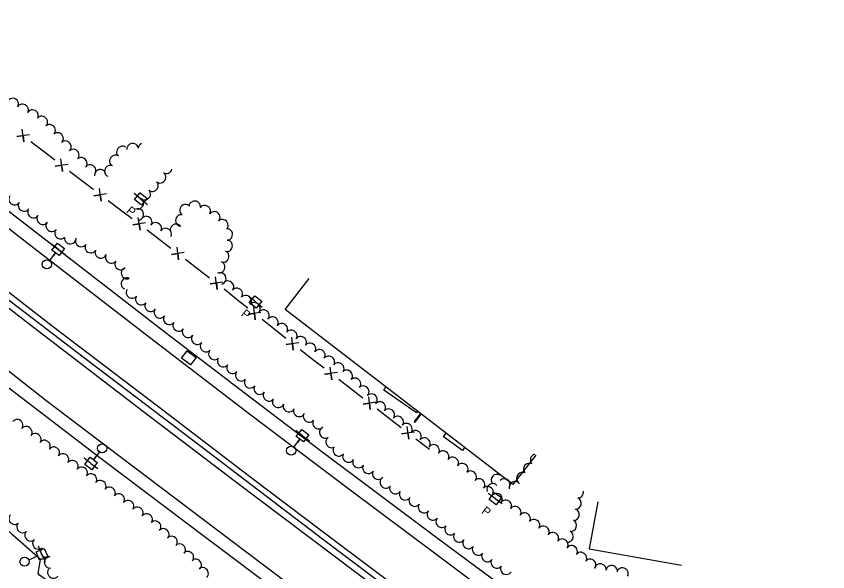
# Model space of a CAD drawing. Extents: x 1746010 to 1754829, y 655801 to 663091.
# Drawn here: x 1749717 to 1750426, y 660347 to 660832 of the extents above; entities that cross this region are included whole.
import ezdxf

# ---------------------------------------------------------------- set-up
doc = ezdxf.new("R2010")
doc.units = 0
for name, color, linetype in [('SURVEY - AERIAL SURVEY - Photo Control - Points - Locators', 7, 'Continuous'), ('SURVEY - AERIAL SURVEY - Photo Control - Points - Numbers', 7, 'Continuous'), ('SURVEY - CENTERLINE - Existing Roads - Development', 7, 'Continuous'), ('SURVEY - CENTERLINE - Existing Roads Curve Text', 7, 'Continuous'), ('SURVEY - CENTERLINE - Existing Roads Text', 7, 'Continuous'), ('SURVEY - CENTERLINE - Preliminary - Development', 7, 'Continuous')]:
    doc.layers.add(name, color=color, linetype=linetype)

msp = doc.modelspace()

# ---------------------------------------------------------------- linework, layer by layer
at = {"layer": 'SURVEY - AERIAL SURVEY - Photo Control - Points - Locators'}
for points in [[(1749387.11, 660899.35), (1749486.53, 660821.3), (1749560.37, 660763.13), (1749636.02, 660704.45), (1749732.4, 660629.58), (1749833.07, 660551.99), (1749920.33, 660484.88), (1750008.5, 660418.55), (1750084.45, 660361.56), (1750166.82, 660299.99), (1750252.84, 660236.3), (1750339.47, 660172.61), (1750424.46, 660110.17), (1750505.09, 660051.79), (1750510.03, 660048.27)], [(1750422.34, 660058.69), (1750341.81, 660116.67), (1750243.85, 660188.2), (1750158.07, 660251.54), (1750079.76, 660310), (1749998.95, 660370.82), (1749924.19, 660427.29), (1749840.05, 660491.49), (1749747.97, 660561.59), (1749667.56, 660623.87), (1749593.96, 660681.21), (1749510.38, 660746.53), (1749431.04, 660809.06), (1749359.66, 660865.36)], [(1749353.21, 660856.72), (1749450.09, 660780.53), (1749529.69, 660717.36), (1749638.4, 660632.78), (1749725.25, 660565.49), (1749826.74, 660487.69), (1749908.21, 660425.76), (1750015.78, 660344.74), (1750134.74, 660255.49), (1750241.73, 660176.3), (1750327.29, 660113.27), (1750398.53, 660061.52)], [(1750309.34, 660072.12), (1750268.26, 660102.16), (1750202.16, 660151.04), (1750125.31, 660207.81), (1750054.71, 660260.76), (1749978.89, 660317.54), (1749904.25, 660374.13), (1749807.5, 660447.32), (1749742.59, 660496.65), (1749689.97, 660537.57), (1749628.45, 660585.34), (1749555.8, 660641.5), (1749484.89, 660697.07), (1749405.47, 660759.79), (1749328.25, 660820.51)], [(1750288.61, 660074.58), (1750206.58, 660134.59), (1750105.78, 660208.88), (1750014.16, 660277.34), (1749883.11, 660375.92), (1749790.93, 660445.43), (1749702.19, 660513.29), (1749634.54, 660565.49), (1749547.88, 660632.78), (1749453.06, 660707.08), (1749311.71, 660816.35)], [(1749949.53, 660142.04), (1749959.68, 660175.76), (1749908.29, 660214.04), (1749859.35, 660250.31), (1749801, 660295.27), (1749769.71, 660320.03), (1749752.54, 660333.06), (1749741.05, 660341.05), (1749737.1, 660343.79), (1749735.68, 660345.35), (1749737.91, 660357.63), (1749713.32, 660379), (1749684.22, 660407.06), (1749658.62, 660430.58), (1749636.39, 660450.84), (1749625.75, 660457.9), (1749494.88, 660556.97)]]:
    msp.add_lwpolyline(points, dxfattribs=at)
at = {"layer": 'SURVEY - AERIAL SURVEY - Photo Control - Points - Numbers'}
for points in [[(1750365.71, 660168.08), (1750350.37, 660178.69), (1750287.2, 660225.82), (1750205.37, 660286.01), (1750139.45, 660335.41), (1750086.68, 660374.49), (1749983.6, 660451.73), (1749923.2, 660497.58), (1749846.86, 660555.87), (1749777.3, 660609.82), (1749717.93, 660655.7), (1749636.62, 660718.64), (1749570.63, 660769.87), (1749510.15, 660817.71), (1749441.97, 660871.04), (1749371.15, 660927.67)], [(1749348.39, 660867.21), (1749450.14, 660787.41), (1749578.82, 660686.52), (1749682.3, 660605.65), (1749779.99, 660530.78), (1749879.01, 660455.62), (1749985.38, 660374.75), (1750084.31, 660300.06), (1750202.67, 660211.89), (1750354.74, 660100.39), (1750409.77, 660060.18)]]:
    msp.add_lwpolyline(points, dxfattribs=at)
at = {"layer": 'SURVEY - CENTERLINE - Existing Roads - Development'}
for points in [[(1749728.19, 660728.84), (1749717.05, 660727.32), (1749722.58, 660728.11), (1749723.31, 660722.5), (1749721.92, 660733.66)], [(1749741.31, 660713.59), (1749729.41, 660722.73)], [(1749750.35, 660706.64), (1749741.31, 660713.59)], [(1749761.89, 660702.94), (1749750.75, 660701.42), (1749756.28, 660702.21), (1749757.01, 660696.6), (1749755.62, 660707.76)], [(1749775.01, 660687.69), (1749763.11, 660696.83)], [(1749784.06, 660680.76), (1749781.98, 660682.33), (1749775.01, 660687.69)], [(1749795.64, 660677.2), (1749784.52, 660675.54), (1749790.04, 660676.4), (1749790.84, 660670.8), (1749789.32, 660681.94)], [(1749808.94, 660662.1), (1749796.95, 660671.1)], [(1749818.06, 660655.26), (1749808.94, 660662.1)], [(1749829.64, 660651.7), (1749818.52, 660650.04), (1749824.04, 660650.9), (1749824.84, 660645.3), (1749823.32, 660656.44)], [(1749842.82, 660636.43), (1749830.92, 660645.56)], [(1749851.86, 660629.49), (1749842.82, 660636.43)], [(1749863.4, 660625.8), (1749852.26, 660624.26), (1749857.79, 660625.06), (1749858.53, 660619.45), (1749857.14, 660630.61)], [(1749876.53, 660610.55), (1749864.64, 660619.69)], [(1749885.58, 660603.61), (1749876.53, 660610.55)], [(1749897.12, 660599.92), (1749885.98, 660598.39), (1749891.51, 660599.18), (1749892.25, 660593.57), (1749890.85, 660604.73)], [(1750170.45, 660448.8), (1750150.63, 660423.04), (1749951.68, 660576.14), (1749972.51, 660603.21)], [(1749910.01, 660584.37), (1749898.28, 660593.71)], [(1749918.93, 660577.26), (1749910.01, 660584.37)], [(1749930.4, 660573.37), (1749919.24, 660572.03), (1749924.78, 660572.73), (1749925.42, 660567.11), (1749924.22, 660578.29)], [(1749943.26, 660557.89), (1749931.53, 660567.23)], [(1749952.18, 660550.79), (1749943.26, 660557.89)], [(1749963.65, 660546.89), (1749952.49, 660545.56), (1749958.03, 660546.25), (1749958.67, 660540.63), (1749957.47, 660551.81)], [(1749976.69, 660531.64), (1749964.82, 660540.82)], [(1749985.71, 660524.67), (1749976.69, 660531.64)], [(1749997.24, 660520.94), (1749986.09, 660519.44), (1749991.62, 660520.22), (1749992.34, 660514.61), (1749990.98, 660525.77)], [(1750010.32, 660505.65), (1749998.45, 660514.83)], [(1750019.34, 660498.68), (1750010.32, 660505.65)], [(1750067.33, 660487.14), (1750066.4, 660485.89), (1750037.81, 660505.57), (1750039.75, 660508.37)], [(1750030.86, 660494.95), (1750019.72, 660493.45), (1750025.25, 660494.23), (1750025.97, 660488.62), (1750024.61, 660499.78)], [(1750043.95, 660479.66), (1750032.08, 660488.83)], [(1750069.71, 660485.31), (1750064.21, 660478.11), (1750065.09, 660477.64), (1750070.48, 660484.72)], [(1750052.97, 660472.69), (1750043.95, 660479.66)], [(1750064.49, 660468.96), (1750053.35, 660467.46), (1750058.88, 660468.24), (1750059.6, 660462.63), (1750058.24, 660473.79)], [(1750077.57, 660453.67), (1750065.71, 660462.84)], [(1750108.38, 660455.55), (1750106.49, 660452.94), (1750090.01, 660464.82), (1750092.3, 660467.92)], [(1750224.62, 660407.89), (1750217.31, 660366.96), (1750297.92, 660352.56)]]:
    msp.add_lwpolyline(points, dxfattribs=at)
at = {"layer": 'SURVEY - CENTERLINE - Existing Roads Curve Text'}
for p, q in [((1749825.49, 660672.65), (1749819.7, 660677.41)), ((1749825.49, 660672.65), (1749831.28, 660667.88)), ((1749753.37, 660628.73), (1749747.38, 660633.25)), ((1749753.37, 660628.73), (1749759.35, 660624.2)), ((1749745.77, 660618.68), (1749751.01, 660625.62)), ((1749750.77, 660625.3), (1749748.84, 660622.75)), ((1749925.62, 660582.69), (1749919.76, 660587.37)), ((1749925.62, 660582.69), (1749931.48, 660578.01)), ((1749966.8, 660465.76), (1749960.83, 660470.3)), ((1749966.8, 660465.76), (1749972.76, 660461.21)), ((1749959.17, 660455.73), (1749964.43, 660462.65)), ((1749964.19, 660462.33), (1749962.25, 660459.79)), ((1749789.44, 660451.62), (1749784.24, 660444.64)), ((1749781.91, 660441.52), (1749775.89, 660446)), ((1749781.91, 660441.52), (1749787.92, 660437.03)), ((1749784.48, 660444.96), (1749786.39, 660447.53)), ((1750135.17, 660410.81), (1750129.08, 660415.2)), ((1750135.17, 660410.81), (1750141.25, 660406.43)), ((1749739.12, 660362.19), (1749736.18, 660369.09)), ((1749727.53, 660357.25), (1749735.53, 660360.66)), ((1749735.16, 660360.5), (1749732.22, 660359.25)), ((1749739.12, 660362.19), (1749742.06, 660355.29))]:
    msp.add_line(p, q, dxfattribs=at)
for points in [[(1749824.96, 660678.14), (1749830.98, 660673.18), (1749826.02, 660667.16), (1749820, 660672.11)], [(1749758.83, 660629.49), (1749754.12, 660623.27), (1749747.9, 660627.97), (1749752.61, 660634.19)], [(1749925, 660588.17), (1749931.1, 660583.3), (1749926.23, 660577.21), (1749920.14, 660582.08)], [(1749972.26, 660466.5), (1749967.54, 660460.29), (1749961.33, 660465.01), (1749966.05, 660471.22)], [(1749776.45, 660440.72), (1749781.11, 660446.98), (1749787.36, 660442.31), (1749782.7, 660436.06)], [(1750134.29, 660416.26), (1750140.61, 660411.7), (1750136.05, 660405.37), (1750129.72, 660409.93)], [(1749744.24, 660360.13), (1749737.06, 660357.07), (1749734, 660364.25), (1749741.18, 660367.31)]]:
    msp.add_lwpolyline(points, close=True, dxfattribs=at)
for centre in [(1749743.41, 660615.57), (1749791.77, 660454.75), (1749956.8, 660452.62), (1749723.94, 660355.72)]:
    msp.add_circle(centre, 4, dxfattribs=at)
at = {"layer": 'SURVEY - CENTERLINE - Existing Roads Text'}
for centre, start, end in [((1750170.91, 660444.55), 105.19083, 221.43986), ((1750164.9, 660436.58), 64.64642, 221.43986), ((1750136.66, 660426.89), 59.10609, 215.89953), ((1750143.15, 660423.14), 340.65434, 137.44778), ((1750158.9, 660428.6), 64.64642, 221.43986), ((1750132.88, 660418.79), 43.1829, 199.97634), ((1750152.33, 660420.63), 36.7632, 193.55664), ((1750207.05, 660416.52), 270.88416, 9.00064), ((1750205.23, 660406.7), 270.88416, 67.6776), ((1750203.42, 660396.88), 270.88416, 67.6776), ((1750201.05, 660387.3), 264.73788, 61.53132), ((1750198.2, 660377.72), 264.73788, 61.53132)]:
    msp.add_arc(centre, 5.13, start, end, dxfattribs=at)
for centre, major_axis, start_param, end_param in [((1749713.78, 660755.9), (4.15, -2.79), 0, 3.141593), ((1749722.36, 660750.79), (4.34, -2.48), 0, 3.141593), ((1749731.02, 660745.83), (4.34, -2.48), 0, 3.141593), ((1749739.17, 660740.21), (3.45, -3.62), 0, 3.141593), ((1749746.07, 660732.98), (3.45, -3.62), 0, 3.141593), ((1749752.97, 660725.74), (3.45, -3.62), 0, 3.141593), ((1749759.87, 660718.51), (3.45, -3.62), 0, 3.141593), ((1749809.17, 660713.91), (3.08, 3.94), 0, 3.141593), ((1749818.36, 660716.55), (4.95, 0.71), 0, 3.141593), ((1749828.31, 660716.85), (5, -0.21), 2.077481, 3.141593), ((1749766.78, 660711.28), (3.45, -3.62), 0, 3.141593), ((1749803.01, 660706.04), (3.08, 3.94), 0, 3.141593), ((1749773.68, 660704.05), (3.45, -3.62), 0, 3.141593), ((1749781.44, 660697.81), (4.11, -2.85), 0, 3.141593), ((1749789.99, 660693.73), (4.91, 0.96), 0, 3.141593), ((1749798.64, 660697.1), (2, 4.58), 0, 3.141593), ((1749848.1, 660699.8), (-2.79, -4.15), 0, 1.920604), ((1749842.51, 660691.52), (-2.79, -4.15), 0, 3.141593), ((1749835.88, 660684.07), (-3.38, -3.68), 0, 3.141593), ((1749829.14, 660676.72), (-3.38, -3.68), 0, 3.141593), ((1749715.03, 660672.3), (-4.01, 2.99), 0, 3.141593), ((1749723.3, 660666.69), (-4.16, 2.77), 0, 3.141593), ((1749823.17, 660668.79), (-2.43, -4.37), 0, 3.141593), ((1749864.29, 660663.01), (2.98, 4.01), 0, 3.141593), ((1749872.61, 660666.14), (5, -0.19), 0, 3.141593), ((1749731.54, 660661.02), (-4.07, 2.91), 0, 3.141593), ((1749823.2, 660659.21), (0.76, -4.94), 0, 3.141593), ((1749881.49, 660662.32), (4.18, -2.75), 0, 3.141593), ((1749889.84, 660656.83), (4.18, -2.75), 0, 3.141593), ((1749739.68, 660655.21), (-4.07, 2.91), 0, 3.141593), ((1749830.39, 660652.74), (4, -3), 0, 3.141593), ((1749860.6, 660653.96), (1.02, 4.9), 0, 3.141593), ((1749896.95, 660649.9), (3.57, -3.5), 0, 3.141593), ((1749747.49, 660648.97), (-3.89, 3.15), 0, 3.141593), ((1749838.71, 660647.23), (4.36, -2.45), 0, 3.141593), ((1749847.42, 660642.33), (4.36, -2.45), 0, 3.141593), ((1749856.12, 660645.98), (4.37, 2.44), 0, 3.141593), ((1749755.16, 660642.56), (-3.74, 3.32), 0, 3.141593), ((1749900.91, 660641.66), (-0.05, -5), 0, 3.141593), ((1749763.69, 660638.11), (-4.91, 0.97), 0, 3.141593), ((1749773.25, 660635.71), (-4.2, 2.71), 0, 3.141593), ((1749781.65, 660630.28), (-4.2, 2.71), 0, 3.141593), ((1749900.81, 660631.75), (-0.05, -5), 0, 3.141593), ((1749790.52, 660625.71), (-4.54, 2.09), 0, 3.141593), ((1749897.7, 660622.34), (-1.79, -4.67), 0, 3.141593), ((1749799.45, 660621.26), (-4.13, 2.82), 0, 3.141593), ((1749807.71, 660615.61), (-4.13, 2.82), 0, 3.141593), ((1749813.2, 660607.71), (-2.42, 4.38), 0, 3.141593), ((1749894.13, 660613), (-1.79, -4.67), 0, 3.141593), ((1749895.28, 660603.27), (0.94, -4.91), 0, 3.141593), ((1749813.07, 660598.8), (1.96, 4.6), 0, 3.141593), ((1749901.77, 660596.21), (3.88, -3.16), 0, 3.141593), ((1749817.54, 660590.7), (-4.07, 2.9), 0, 3.141593), ((1749909.52, 660589.9), (3.88, -3.16), 0, 3.141593), ((1749825.69, 660584.9), (-4.07, 2.9), 0, 3.141593), ((1749917.28, 660583.59), (3.88, -3.16), 0, 3.141593), ((1749833.84, 660579.13), (-4.09, 2.88), 0, 3.141593), ((1749842, 660573.37), (-4.09, 2.88), 0, 3.141593), ((1749925.04, 660577.28), (3.88, -3.16), 0, 3.141593), ((1749932.8, 660570.97), (3.88, -3.16), 0, 3.141593), ((1749850.19, 660567.66), (-4.11, 2.85), 0, 3.141593), ((1749940.66, 660564.8), (4.11, -2.85), 0, 3.141593), ((1749858.39, 660561.96), (-4.11, 2.85), 0, 3.141593), ((1749948.87, 660559.1), (4.11, -2.85), 0, 3.141593), ((1749866.64, 660556.31), (-4.13, 2.82), 0, 3.141593), ((1749957.08, 660553.39), (4.11, -2.85), 0, 3.141593), ((1749874.66, 660550.35), (-3.83, 3.21), 0, 3.141593), ((1749965.29, 660547.69), (4.11, -2.85), 0, 3.141593), ((1749882.3, 660543.9), (-3.63, 3.44), 0, 3.141593), ((1749973.5, 660541.98), (4.1, -2.86), 0, 3.141593), ((1749981.7, 660536.27), (4.1, -2.86), 0, 3.141593), ((1749889.56, 660537.02), (-3.63, 3.44), 0, 3.141593), ((1749897.24, 660530.66), (-4.07, 2.9), 0, 3.141593), ((1749989.9, 660530.55), (4.1, -2.86), 0, 3.141593), ((1749905.39, 660524.87), (-4.07, 2.9), 0, 3.141593), ((1749998.11, 660524.83), (4.1, -2.86), 0, 3.141593), ((1749913.01, 660518.39), (-3.79, 3.26), 0, 3.141593), ((1750005.62, 660518.28), (3.61, -3.46), 0, 3.141593), ((1749920.86, 660512.23), (-4.17, 2.77), 0, 3.141593), ((1750012.83, 660511.35), (3.61, -3.46), 0, 3.141593), ((1749929.19, 660506.7), (-4.17, 2.77), 0, 3.141593), ((1750020.05, 660504.43), (3.61, -3.46), 0, 3.141593), ((1749937.3, 660500.87), (-4.02, 2.98), 0, 3.141593), ((1750027.26, 660497.5), (3.61, -3.46), 0, 3.141593), ((1749945.37, 660495), (-4.66, 1.8), 0, 3.141593), ((1749954.7, 660491.4), (-4.66, 1.8), 0, 3.141593), ((1750034.52, 660490.62), (3.89, -3.15), 0, 3.141593), ((1749963.73, 660487.21), (-4.51, 2.15), 0, 3.141593), ((1749972.36, 660482.27), (-4.09, 2.88), 0, 3.141593), ((1750042.29, 660484.33), (3.89, -3.15), 0, 3.141593), ((1749717.69, 660475.15), (3.96, -3.06), 0, 3.141593), ((1749980.54, 660476.51), (-4.09, 2.88), 0, 3.141593), ((1750050.07, 660478.04), (3.89, -3.15), 0, 3.141593), ((1750057.84, 660471.75), (3.89, -3.15), 0, 3.141593), ((1749725.6, 660469.05), (3.96, -3.06), 0, 3.141593), ((1749986.42, 660468.48), (-2.84, 4.11), 0, 3.141593), ((1750065.61, 660465.46), (3.89, -3.15), 0, 3.141593), ((1749733.5, 660462.94), (3.96, -3.06), 0, 3.141593), ((1749991.95, 660460.16), (-2.71, 4.2), 0, 3.141593), ((1750073.39, 660459.17), (3.89, -3.15), 0, 3.141593), ((1749741.54, 660456.99), (4.06, -2.92), 0, 3.141593), ((1749749.65, 660451.15), (4.06, -2.92), 0, 3.141593), ((1750081.37, 660453.17), (4.19, -2.73), 0, 3.141593), ((1749757.76, 660445.31), (4.06, -2.92), 0, 3.141593), ((1749998.34, 660452.72), (-4.17, 2.76), 0, 3.141593), ((1750006.74, 660447.31), (-4.39, 2.4), 0, 3.141593), ((1750089.75, 660447.72), (4.19, -2.73), 0, 3.141593), ((1749765.88, 660439.47), (4.06, -2.92), 0, 3.141593), ((1750015.51, 660442.5), (-4.39, 2.4), 0, 3.141593), ((1750098.13, 660442.27), (4.19, -2.73), 0, 3.141593), ((1750106.5, 660436.81), (4.19, -2.73), 0, 3.141593), ((1749773.99, 660433.63), (4.06, -2.92), 0, 3.141593), ((1750024.15, 660437.47), (-4.29, 2.57), 0, 3.141593), ((1750032.72, 660432.33), (-4.29, 2.57), 0, 3.141593), ((1750113.89, 660430.11), (3.68, -3.39), 0, 3.141593), ((1749782.1, 660427.79), (4.06, -2.92), 0, 3.141593), ((1749790.22, 660421.95), (4.06, -2.92), 0, 3.141593), ((1750039.3, 660424.8), (-3.28, 3.78), 0, 3.141593), ((1750121.23, 660423.35), (3.68, -3.39), 0, 3.141593), ((1749798.33, 660416.11), (4.06, -2.92), 0, 3.141593), ((1750047.79, 660419.62), (-4.36, 2.45), 0, 3.141593), ((1750128.57, 660416.58), (3.68, -3.39), 0, 3.141593), ((1749806.44, 660410.27), (4.06, -2.92), 0, 3.141593), ((1750056.28, 660414.35), (-4.18, 2.75), 0, 3.141593), ((1750136.41, 660410.57), (3.99, -3.02), 0, 3.141593), ((1749814.56, 660404.43), (4.06, -2.92), 0, 3.141593), ((1750064.61, 660408.81), (-4.08, 2.89), 0, 3.141593), ((1750144.49, 660404.79), (4.13, -2.82), 0, 3.141593), ((1749822.67, 660398.59), (4.06, -2.92), 0, 3.141593), ((1750072.77, 660403.03), (-4.08, 2.89), 0, 3.141593), ((1750080.55, 660396.77), (-3.84, 3.2), 0, 3.141593), ((1750152.73, 660399.15), (4.13, -2.82), 0, 3.141593), ((1750160.97, 660393.51), (4.13, -2.82), 0, 3.141593), ((1749715.08, 660393.01), (-3.46, 3.61), 0, 3.141593), ((1749830.78, 660392.74), (4.06, -2.92), 0, 3.141593), ((1750088.2, 660390.32), (-3.81, 3.24), 0, 3.141593), ((1750169.18, 660387.8), (4.1, -2.86), 0, 3.141593), ((1749722, 660385.8), (-3.46, 3.61), 0, 3.141593), ((1749838.27, 660386.39), (3.65, -3.41), 0, 3.141593), ((1749845.4, 660379.73), (3.65, -3.41), 0, 3.141593), ((1750095.81, 660383.83), (-3.81, 3.24), 0, 3.141593), ((1750177.38, 660382.07), (4.1, -2.86), 0, 3.141593), ((1749728.92, 660378.59), (-3.46, 3.61), 0, 3.141593), ((1749852.53, 660373.08), (3.65, -3.41), 0, 3.141593), ((1750103.54, 660377.5), (-4.1, 2.87), 0, 3.141593), ((1750185.59, 660376.36), (4.13, -2.82), 0, 3.141593), ((1749735.84, 660371.38), (-3.46, 3.61), 0, 3.141593), ((1749859.65, 660366.42), (3.65, -3.41), 0, 3.141593), ((1750111.74, 660371.77), (-4.1, 2.87), 0, 3.141593), ((1750193.83, 660370.72), (4.13, -2.82), 0, 3.141593), ((1749742.76, 660364.17), (-3.46, 3.61), 0, 3.141593), ((1749866.78, 660359.77), (3.65, -3.41), 0, 3.141593), ((1750119.92, 660366.06), (-4.11, 2.85), 0, 3.141593), ((1750202.01, 660364.98), (4.05, -2.93), 0, 3.141593), ((1750210.11, 660359.11), (4.05, -2.93), 0, 3.141593), ((1749745.87, 660355.07), (-1.15, 4.87), 0, 3.141593), ((1749873.69, 660352.98), (3.18, -3.86), 0, 3.141593), ((1750128.09, 660360.39), (-4.11, 2.85), 0, 3.141593), ((1750136.29, 660354.7), (-4.11, 2.85), 0, 3.141593), ((1750218.21, 660353.24), (4.05, -2.93), 0, 3.141593), ((1749879.74, 660345.65), (3.18, -3.86), 0, 3.141593), ((1750144.65, 660349.24), (-4.35, 2.46), 0, 3.141593), ((1750226.97, 660349.03), (4.95, -0.71), 0, 3.141593), ((1750236.86, 660347.61), (4.95, -0.71), 0, 3.141593), ((1750246.46, 660345.55), (4.23, -2.67), 0, 3.141593), ((1749748.92, 660346.03), (-3.95, 3.06), 0, 3.141593)]:
    msp.add_ellipse(centre, major_axis=major_axis, ratio=0.940188, start_param=start_param, end_param=end_param, dxfattribs=at)
at = {"layer": 'SURVEY - CENTERLINE - Preliminary - Development'}
msp.add_line((1749867.44, 660533.83), (1749867.44, 660533.83), dxfattribs=at)
msp.add_lwpolyline([(1749861.04, 660533.65), (1749865.86, 660540.04), (1749873.84, 660534.01), (1749869.03, 660527.62), (1749861.04, 660533.65)], dxfattribs=at)

# ---------------------------------------------------------------- texts
at = {"layer": 'SURVEY - CENTERLINE - Existing Roads Curve Text'}
for rotation, p in [(320.55028, (1749812.1, 660661.26)), (321.37968, (1749912.4, 660571.11)), (324.21123, (1750122.54, 660398.59))]:
    msp.add_text('P', height=7.48, rotation=rotation, dxfattribs=at).set_placement(p)

doc.saveas('drawing.dxf')
